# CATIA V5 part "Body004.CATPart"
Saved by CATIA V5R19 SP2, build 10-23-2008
Part number: Body004
Definition: design
Nomenclature: Body004
Source: Unknown
Bounding box of the stored display mesh (mm): x -5 to 7.5, y -70.49 to -63.49, z 0 to 2
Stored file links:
  Z:\fausse table rondelle-20220905T211342Z-001\fausse table rondelle\Body004.CATPart
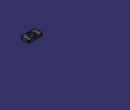
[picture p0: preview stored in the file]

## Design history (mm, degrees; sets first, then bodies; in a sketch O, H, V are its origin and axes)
AxisSystem1: origin (0, 0, 0), X (1, 0, 0), Y (0, 1, 0), Z (0, 0, 1)
Body1 "MANIFOLD_SOLID_BREP #35528" (main body)
  Solid1: solid without history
